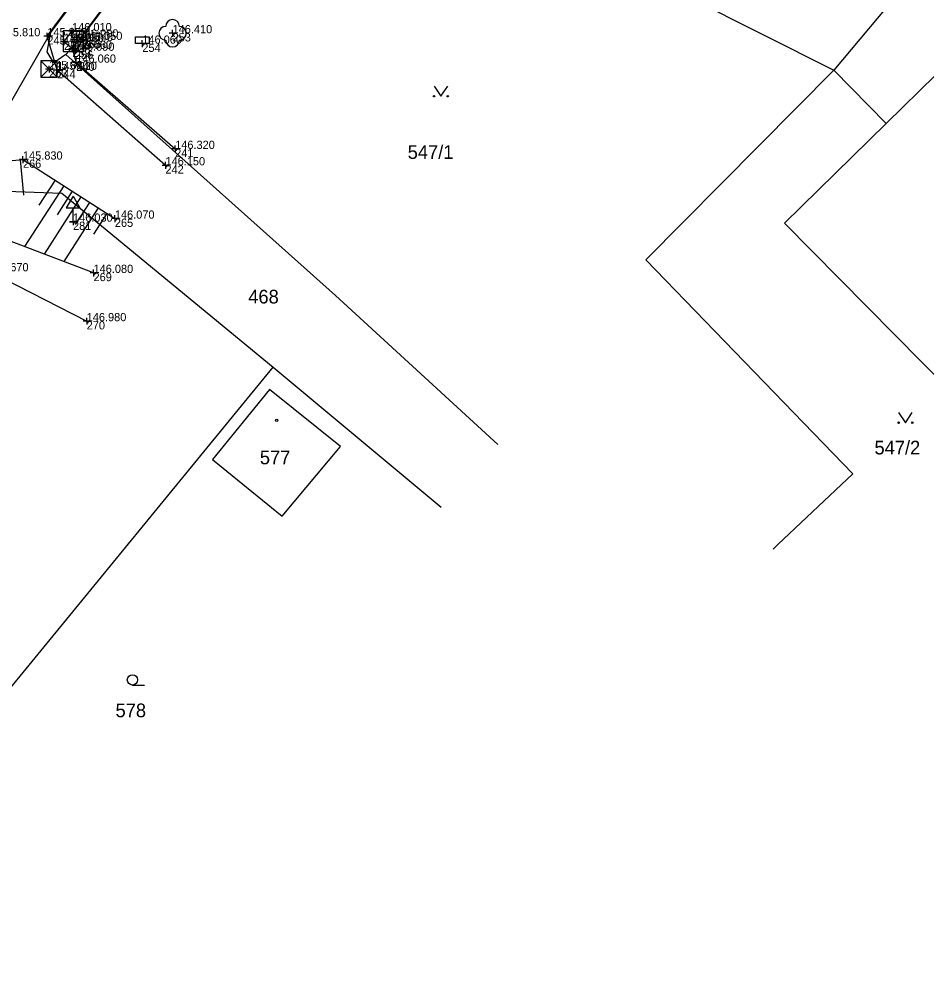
# Model space of a CAD drawing. Extents: x -748509 to -748117, y -967868 to -967533.
# Drawn here: x -748315.7 to -748249.3, y -967744.6 to -967674.7 of the extents above; entities that cross this region are included whole.
import ezdxf

# ---------------------------------------------------------------- set-up
doc = ezdxf.new("R2010")
doc.units = 0
for name, color, linetype in [('Body polohopisu', 7, 'Continuous'), ('Doplňkové značky', 7, 'Continuous'), ('KM', 7, 'Continuous'), ('Ploty_opěrné zdi', 7, 'Continuous'), ('Rozhraní ploch', 7, 'Continuous'), ('Stromy_porost', 7, 'Continuous'), ('Vnitřní kresba', 7, 'Continuous'), ('Výškopis', 7, 'Continuous'), ('Výšky bodů', 7, 'Continuous'), ('Značky IS', 7, 'Continuous'), ('Čísla bodů', 7, 'Continuous')]:
    doc.layers.add(name, color=color, linetype=linetype)

msp = doc.modelspace()

# ---------------------------------------------------------------- linework, layer by layer
at = {"layer": 'Body polohopisu'}
for p, q in [((-748311.83, -967675.62), (-748312.08, -967675.62)), ((-748311.83, -967675.62), (-748311.83, -967675.37)), ((-748311.83, -967675.62), (-748311.58, -967675.62)), ((-748311.83, -967675.62), (-748311.83, -967675.87)), ((-748304.48, -967675.77), (-748304.48, -967675.52)), ((-748313.64, -967675.99), (-748313.89, -967675.99)), ((-748313.64, -967675.99), (-748313.64, -967675.74)), ((-748313.64, -967675.99), (-748313.39, -967675.99)), ((-748313.64, -967675.99), (-748313.64, -967676.24)), ((-748312.42, -967676.39), (-748312.42, -967676.14)), ((-748311.74, -967676.35), (-748311.99, -967676.35)), ((-748311.74, -967676.35), (-748311.74, -967676.1)), ((-748311.74, -967676.35), (-748311.49, -967676.35)), ((-748311.74, -967676.35), (-748311.74, -967676.6)), ((-748311.34, -967676.08), (-748311.59, -967676.08)), ((-748311.34, -967676.08), (-748311.34, -967675.83)), ((-748311.34, -967676.08), (-748311.09, -967676.08)), ((-748311.34, -967676.08), (-748311.34, -967676.33)), ((-748311.05, -967676.26), (-748311.3, -967676.26)), ((-748311.05, -967676.26), (-748311.05, -967676.01)), ((-748311.05, -967676.26), (-748310.8, -967676.26)), ((-748311.05, -967676.26), (-748311.05, -967676.51)), ((-748306.69, -967676.53), (-748306.69, -967676.28)), ((-748304.48, -967675.77), (-748304.73, -967675.77)), ((-748304.48, -967675.77), (-748304.23, -967675.77)), ((-748304.48, -967675.77), (-748304.48, -967676.02)), ((-748312.42, -967676.39), (-748312.67, -967676.39)), ((-748312.42, -967676.39), (-748312.17, -967676.39)), ((-748312.42, -967676.39), (-748312.42, -967676.64)), ((-748311.81, -967676.91), (-748312.06, -967676.91)), ((-748311.81, -967676.91), (-748311.81, -967676.66)), ((-748311.81, -967676.91), (-748311.56, -967676.91)), ((-748311.81, -967676.91), (-748311.81, -967677.16)), ((-748311.63, -967677.05), (-748311.63, -967676.8)), ((-748306.69, -967676.53), (-748306.94, -967676.53)), ((-748306.69, -967676.53), (-748306.44, -967676.53)), ((-748306.69, -967676.53), (-748306.69, -967676.78)), ((-748311.63, -967677.05), (-748311.88, -967677.05)), ((-748311.63, -967677.05), (-748311.38, -967677.05)), ((-748311.63, -967677.05), (-748311.63, -967677.3)), ((-748311.52, -967677.92), (-748311.52, -967677.67)), ((-748313.51, -967678.39), (-748313.76, -967678.39)), ((-748313.51, -967678.39), (-748313.51, -967678.14)), ((-748313.51, -967678.39), (-748313.26, -967678.39)), ((-748313.51, -967678.39), (-748313.51, -967678.64)), ((-748312.91, -967678.46), (-748312.91, -967678.21)), ((-748311.52, -967677.92), (-748311.77, -967677.92)), ((-748311.52, -967677.92), (-748311.27, -967677.92)), ((-748311.52, -967677.92), (-748311.52, -967678.17)), ((-748312.91, -967678.46), (-748313.16, -967678.46)), ((-748312.91, -967678.46), (-748312.66, -967678.46)), ((-748312.91, -967678.46), (-748312.91, -967678.71)), ((-748304.29, -967684.23), (-748304.29, -967683.98)), ((-748304.29, -967684.23), (-748304.54, -967684.23)), ((-748304.29, -967684.23), (-748304.04, -967684.23)), ((-748304.29, -967684.23), (-748304.29, -967684.48)), ((-748315.42, -967685.01), (-748315.67, -967685.01)), ((-748315.42, -967685.01), (-748315.42, -967684.76)), ((-748315.42, -967685.01), (-748315.17, -967685.01)), ((-748315.42, -967685.01), (-748315.42, -967685.26)), ((-748305, -967685.43), (-748305, -967685.18)), ((-748305, -967685.43), (-748305.25, -967685.43)), ((-748305, -967685.43), (-748304.75, -967685.43)), ((-748305, -967685.43), (-748305, -967685.68)), ((-748311.76, -967689.55), (-748312.01, -967689.55)), ((-748311.76, -967689.55), (-748311.76, -967689.3)), ((-748311.76, -967689.55), (-748311.51, -967689.55)), ((-748311.76, -967689.55), (-748311.76, -967689.8)), ((-748308.7, -967689.33), (-748308.95, -967689.33)), ((-748308.7, -967689.33), (-748308.7, -967689.08)), ((-748308.7, -967689.33), (-748308.45, -967689.33)), ((-748308.7, -967689.33), (-748308.7, -967689.58)), ((-748310.26, -967693.3), (-748310.26, -967693.05)), ((-748310.26, -967693.3), (-748310.51, -967693.3)), ((-748310.26, -967693.3), (-748310.01, -967693.3)), ((-748310.26, -967693.3), (-748310.26, -967693.55)), ((-748310.76, -967696.83), (-748310.76, -967696.58)), ((-748310.76, -967696.83), (-748311.01, -967696.83)), ((-748310.76, -967696.83), (-748310.51, -967696.83)), ((-748310.76, -967696.83), (-748310.76, -967697.08))]:
    msp.add_line(p, q, dxfattribs=at)
at = {"layer": 'Doplňkové značky'}
for p, q in [((-748311.76, -967687.684), (-748312.26, -967688.55)), ((-748311.76, -967687.684), (-748311.26, -967688.55)), ((-748312.26, -967688.55), (-748311.26, -967688.55)), ((-748311.76, -967689.55), (-748311.76, -967688.55)), ((-748312.01, -967689.55), (-748311.51, -967689.55))]:
    msp.add_line(p, q, dxfattribs=at)
at = {"layer": 'KM'}
for p, q in [((-748241.55, -967661.04), (-748256.12, -967678.46)), ((-748266.94, -967673.02), (-748256.12, -967678.46)), ((-748331.65, -967742.34), (-748297.11, -967700.2)), ((-748307.417, -967723.439), (-748306.542, -967723.439))]:
    msp.add_line(p, q, dxfattribs=at)
for points in [[(-748313.39, -967675.71), (-748297.69, -967654.72), (-748296.75, -967652.08), (-748293.15, -967646.97), (-748273.11, -967620.67), (-748270.74, -967620.14)], [(-748312.29, -967677.32), (-748311.09, -967676), (-748309.95, -967674.53), (-748308.07, -967671.98), (-748306.56, -967670.07), (-748304.1, -967666.73), (-748302.66, -967664.83), (-748300.42, -967661.9), (-748298.88, -967659.86), (-748294.18, -967653.84), (-748294.88, -967653.36), (-748293.88, -967651.75)], [(-748320, -967687.2), (-748317.87, -967683.5), (-748313.39, -967675.71)], [(-748312.29, -967677.32), (-748313.16, -967677.93), (-748313.66, -967677.14), (-748313.39, -967675.71)], [(-748280.683, -967705.85), (-748292.56, -967694.95), (-748312.29, -967677.32)], [(-748260.56, -967713.5), (-748260.21, -967713.16), (-748254.73, -967708), (-748269.87, -967692.34), (-748256.12, -967678.46)], [(-748256.12, -967678.46), (-748252.29, -967682.37), (-748259.73, -967689.65), (-748241.64, -967707.97), (-748241.3, -967707.63), (-748237.79, -967710.82)], [(-748285.35, -967679.63), (-748284.85, -967680.38), (-748284.35, -967679.63)], [(-748320, -967687.2), (-748312.57, -967687.46), (-748297.11, -967700.2)], [(-748297.11, -967700.2), (-748284.831, -967710.435)], [(-748296.47, -967711.09), (-748292.2, -967706), (-748297.38, -967701.82), (-748301.55, -967706.95), (-748296.47, -967711.09)], [(-748251.388, -967703.502), (-748250.888, -967704.252), (-748250.388, -967703.502)]]:
    msp.add_lwpolyline(points, dxfattribs=at)
for centre, radius in [((-748285.35, -967680.38), 0.05), ((-748284.35, -967680.38), 0.05), ((-748296.863, -967704.09), 0.0875), ((-748251.388, -967704.252), 0.05), ((-748250.388, -967704.252), 0.05), ((-748307.417, -967723.064), 0.375)]:
    msp.add_circle(centre, radius, dxfattribs=at)
at = {"layer": 'Ploty_opěrné zdi'}
msp.add_lwpolyline([(-748378.66, -967748.92), (-748376.91, -967745.27), (-748368.58, -967737.15), (-748341.64, -967709.04), (-748325.07, -967691.76), (-748317.91, -967693.18), (-748310.76, -967696.83)], dxfattribs=at)
at = {"layer": 'Rozhraní ploch'}
for points in [[(-748305, -967685.43), (-748312.91, -967678.46), (-748313.64, -967675.99), (-748305.57, -967665.09), (-748297.76, -967654.67), (-748296.9, -967652.03), (-748294.12, -967653.15)], [(-748289.04, -967655.72), (-748294.12, -967653.15), (-748298.93, -967659.68), (-748298.52, -967660.02), (-748299.93, -967661.97), (-748300.4, -967661.59), (-748311.81, -967676.91), (-748311.52, -967677.92), (-748304.29, -967684.23)], [(-748311.05, -967676.26), (-748311.63, -967677.05), (-748312.42, -967676.39), (-748311.83, -967675.62)], [(-748379.7, -967759.26), (-748384.32, -967755.05), (-748386.55, -967750.17), (-748369.03, -967731.8), (-748343.77, -967705.84), (-748327.45, -967688.79), (-748321.7, -967685.59), (-748315.42, -967685.01), (-748308.7, -967689.33)]]:
    msp.add_lwpolyline(points, dxfattribs=at)
at = {"layer": 'Stromy_porost'}
msp.add_circle((-748304.48, -967675.77), 0.0005, dxfattribs=at)
for centre, start, end in [((-748304.48, -967675.27), 0, 179.99999), ((-748304.98, -967675.77), 89.99999, 269.99999), ((-748303.98, -967675.77), 270, 89.99999), ((-748304.48, -967676.27), 179.99999, 359.99999)]:
    msp.add_arc(centre, 0.5, start, end, dxfattribs=at)
at = {"layer": 'Vnitřní kresba'}
msp.add_line((-748252.29, -967682.37), (-748248.67, -967678.82), dxfattribs=at)
at = {"layer": 'Výškopis'}
for points in [[(-748315.631, -967685.029), (-748315.392, -967687.611)], [(-748313.074, -967686.518), (-748314.254, -967688.353)], [(-748312.443, -967686.924), (-748315.307, -967691.378)], [(-748311.813, -967687.329), (-748312.924, -967689.058)], [(-748311.182, -967687.735), (-748313.875, -967691.924)], [(-748310.551, -967688.14), (-748311.594, -967689.763)], [(-748309.92, -967688.546), (-748312.442, -967692.469)], [(-748309.289, -967688.951), (-748310.264, -967690.468)], [(-748310.26, -967693.3), (-748319.69, -967689.71), (-748326.66, -967689.92), (-748343.09, -967706.41), (-748368.35, -967732.47), (-748383.21, -967747.7), (-748386, -967750.54)]]:
    msp.add_lwpolyline(points, dxfattribs=at)
at = {"layer": 'Značky IS'}
for p, q in [((-748314.11, -967677.79), (-748312.91, -967678.99)), ((-748312.91, -967677.79), (-748314.11, -967678.99))]:
    msp.add_line(p, q, dxfattribs=at)
for points in [[(-748312.49, -967677.1), (-748310.99, -967677.1), (-748310.99, -967675.6), (-748312.49, -967675.6)], [(-748311.84, -967676.08), (-748311.84, -967675.58), (-748310.84, -967675.58), (-748310.84, -967676.08)], [(-748307.19, -967676.53), (-748307.19, -967676.03), (-748306.19, -967676.03), (-748306.19, -967676.53)], [(-748314.11, -967678.99), (-748312.91, -967678.99), (-748312.91, -967677.79), (-748314.11, -967677.79)]]:
    msp.add_lwpolyline(points, close=True, dxfattribs=at)

# ---------------------------------------------------------------- texts
at = {"layer": 'KM'}
for s, p in [('547/1', (-748287.285, -967684.96)), ('468', (-748298.944, -967695.533)), ('547/2', (-748253.146, -967706.577)), ('577', (-748298.096, -967707.294)), ('578', (-748308.649, -967725.796))]:
    msp.add_text(s, height=1, dxfattribs=at).set_placement(p)
at = {"layer": 'Výšky bodů'}
for s, p in [('145.810', (-748317.05, -967675.99)), ('145.850', (-748313.64, -967675.99)), ('146.010', (-748311.83, -967675.62)), ('146.000', (-748311.34, -967676.08)), ('146.050', (-748311.05, -967676.26)), ('146.410', (-748304.48, -967675.77)), ('146.010', (-748312.42, -967676.39)), ('146.060', (-748311.81, -967676.91)), ('146.540', (-748311.74, -967676.35)), ('146.060', (-748306.69, -967676.53)), ('146.090', (-748311.63, -967677.05)), ('146.060', (-748311.52, -967677.92)), ('145.880', (-748313.51, -967678.39)), ('145.920', (-748312.91, -967678.46)), ('146.320', (-748304.29, -967684.23)), ('145.830', (-748315.42, -967685.01)), ('146.150', (-748305, -967685.43)), ('146.070', (-748308.7, -967689.33)), ('146.030', (-748311.76, -967689.55)), ('146.670', (-748317.91, -967693.18)), ('146.080', (-748310.26, -967693.3)), ('146.980', (-748310.76, -967696.83))]:
    msp.add_text(s, height=0.6, dxfattribs=at).set_placement(p)
at = {"layer": 'Čísla bodů'}
for s, p in [('258', (-748311.83, -967676.22)), ('245', (-748313.64, -967676.59)), ('259', (-748311.74, -967676.95)), ('260', (-748311.34, -967676.68)), ('255', (-748311.05, -967676.86)), ('253', (-748304.48, -967676.37)), ('257', (-748312.42, -967676.99)), ('239', (-748311.81, -967677.51)), ('256', (-748311.63, -967677.65)), ('254', (-748306.69, -967677.13)), ('263', (-748313.51, -967678.99)), ('240', (-748311.52, -967678.52)), ('244', (-748312.91, -967679.06)), ('241', (-748304.29, -967684.83)), ('266', (-748315.42, -967685.61)), ('242', (-748305, -967686.03)), ('281', (-748311.76, -967690.15)), ('265', (-748308.7, -967689.93)), ('269', (-748310.26, -967693.9)), ('270', (-748310.76, -967697.43))]:
    msp.add_text(s, height=0.6, dxfattribs=at).set_placement(p)

doc.saveas('drawing.dxf')
